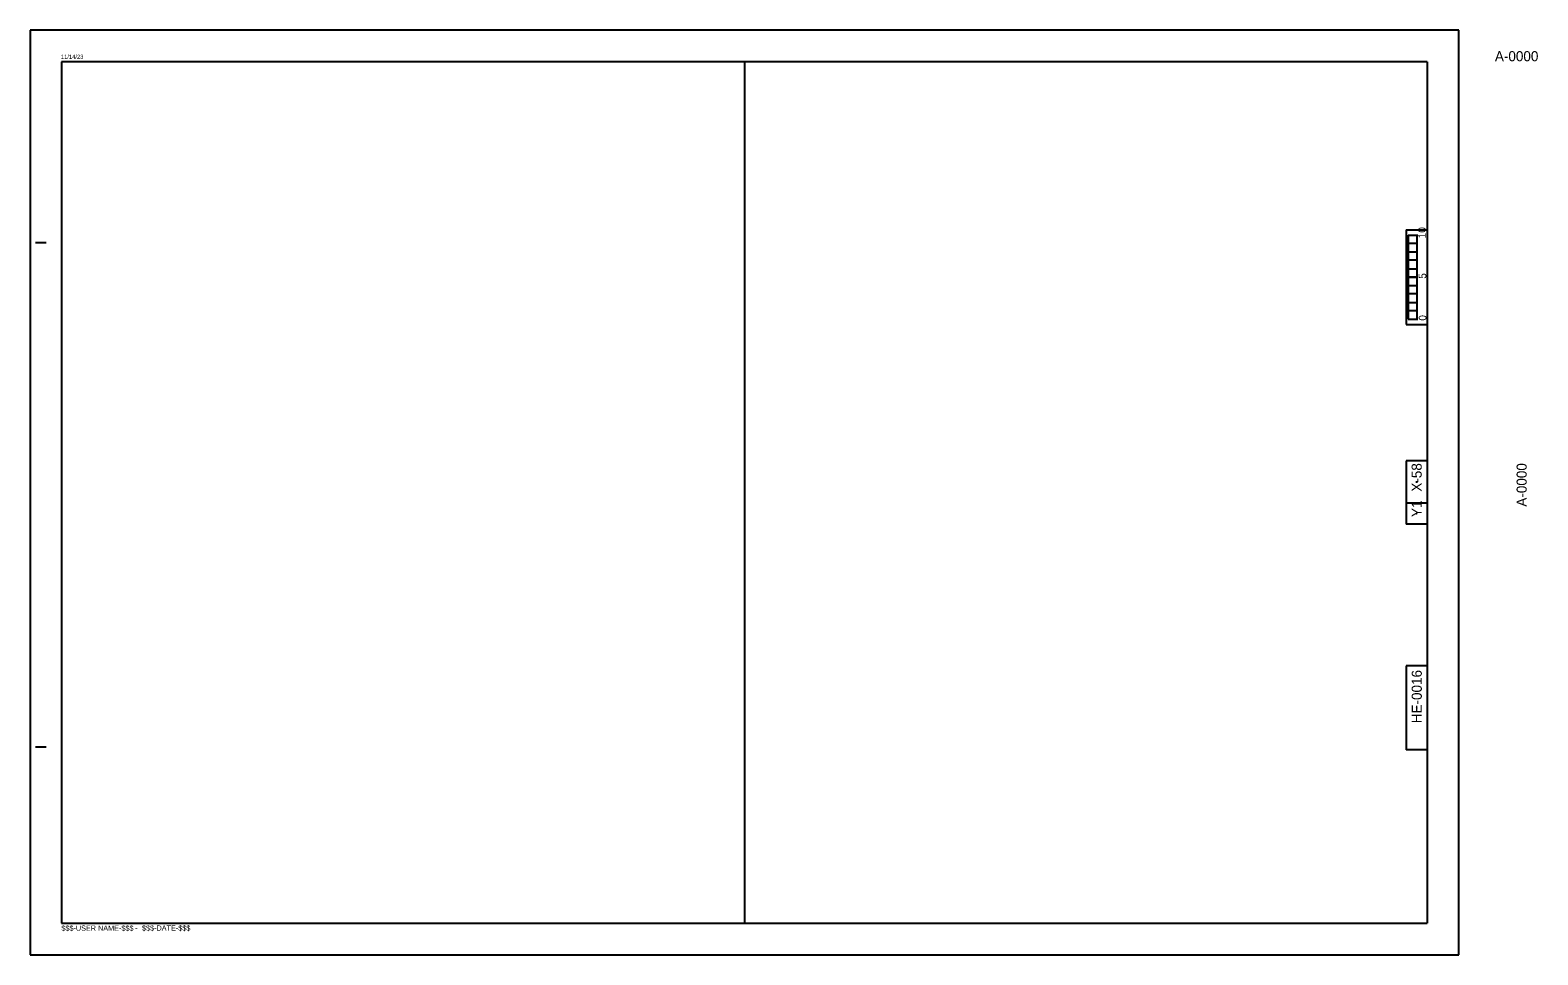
# Model space of a CAD drawing. Extents: x -2.69 to 2.99, y 0 to 1.83.
# Drawn here: x 0 to 2.99, y 0 to 1.833 of the extents above; entities that cross this region are included whole.
import ezdxf

# ---------------------------------------------------------------- set-up
doc = ezdxf.new("R2010")
doc.units = 0
for name, color, linetype in [('P_NCDOT_XS_Sheet_Alignment_Station_Label', 7, 'Continuous'), ('P_NCDOT_XS_Sheet_Annotation_Label', 7, 'Continuous'), ('Sheet_Grid_Major', 7, 'Continuous'), ('Sheet_Grid_Middle', 7, 'Continuous'), ('Sheet_Grid_Minor', 7, 'Continuous')]:
    doc.layers.add(name, color=color, linetype=linetype)

msp = doc.modelspace()

# ---------------------------------------------------------------- linework, layer by layer
at = {"layer": 'P_NCDOT_XS_Sheet_Alignment_Station_Label'}
for p, q in [((2.7333, 1.4271), (2.7522, 1.4271)), ((2.7333, 1.4271), (2.7333, 1.2604)), ((2.7417, 1.4271), (2.7504, 1.4271)), ((2.75, 1.4271), (2.75, 1.2604)), ((2.7333, 1.3437), (2.7522, 1.3437)), ((2.7333, 1.2604), (2.7522, 1.2604)), ((2.7417, 1.2604), (2.7504, 1.2604))]:
    msp.add_line(p, q, dxfattribs=at)
for points in [[(2.7333, 1.4271), (2.75, 1.4271), (2.75, 1.4104), (2.7333, 1.4104)], [(2.7333, 1.3937), (2.75, 1.3937), (2.75, 1.3771), (2.7333, 1.3771)], [(2.7333, 1.3604), (2.75, 1.3604), (2.75, 1.3437), (2.7333, 1.3437)], [(2.7333, 1.3271), (2.75, 1.3271), (2.75, 1.3104), (2.7333, 1.3104)], [(2.7333, 1.2937), (2.75, 1.2937), (2.75, 1.2771), (2.7333, 1.2771)]]:
    msp.add_lwpolyline(points, close=True, dxfattribs=at)
at = {"layer": 'P_NCDOT_XS_Sheet_Annotation_Label'}
for p, q in [((2.8333, 1.8333), (0, 1.8333)), ((0, 1.8333), (0, 0)), ((2.8333, 0), (2.8333, 1.8333)), ((1.4167, 1.7708), (1.4166, 0.0625)), ((0, 0), (2.8333, 0))]:
    msp.add_line(p, q, dxfattribs=at)
for centre in [(2.7499, 1.3437), (2.7499, 0.9375), (2.7499, 0.875), (2.75, 0.4897)]:
    msp.add_circle(centre, 0.0001, dxfattribs=at)
at = {"layer": 'Sheet_Grid_Minor'}
for p, q in [((0.0625, 1.7708), (0.0625, 0.0625)), ((2.7708, 1.7708), (0.0625, 1.7708)), ((0.1027, 1.7844), (0.1027, 1.7844)), ((2.7708, 1.7708), (2.7708, 0.0625)), ((2.7292, 1.4375), (2.7292, 1.25)), ((2.7292, 1.4375), (2.7708, 1.4375)), ((0.0108, 1.4125), (0.0317, 1.4126)), ((2.7292, 1.25), (2.7708, 1.25)), ((2.7292, 0.9792), (2.7292, 0.8542)), ((2.7708, 0.9792), (2.7292, 0.9792)), ((2.7708, 0.8958), (2.7292, 0.8958)), ((2.7708, 0.8542), (2.7292, 0.8542)), ((2.7292, 0.5729), (2.7292, 0.4062)), ((2.7708, 0.5729), (2.7292, 0.5729)), ((0.0109, 0.4125), (0.0317, 0.4125)), ((2.7708, 0.4062), (2.7292, 0.4062)), ((0.0625, 0.0625), (2.7708, 0.0625))]:
    msp.add_line(p, q, dxfattribs=at)

# ---------------------------------------------------------------- texts
at = {"layer": 'P_NCDOT_XS_Sheet_Alignment_Station_Label'}
for s, p in [('10', (2.7679, 1.4206)), ('5', (2.7689, 1.3404)), ('0', (2.7691, 1.2573))]:
    msp.add_text(s, height=0.015, rotation=90, dxfattribs=at).set_placement(p)
at = {"layer": 'Sheet_Grid_Major'}
msp.add_text('A-0000', height=0.02, dxfattribs=at).set_placement((2.9051, 1.7717))
msp.add_text('A-0000', height=0.02, rotation=90, dxfattribs=at).set_placement((2.9681, 0.8886))
at = {"layer": 'Sheet_Grid_Middle'}
for s, p in [('X-58', (2.7599, 0.9183)), ('Y1', (2.76, 0.8681)), ('HE-0016', (2.7601, 0.4592))]:
    msp.add_text(s, height=0.02, rotation=90, dxfattribs=at).set_placement(p)
at = {"layer": 'Sheet_Grid_Minor'}
msp.add_text('11/14/23', height=0.00833, rotation=0, dxfattribs=at).set_placement((0.0609, 1.7764))
for s, height, p in [('$$$-USER NAME-$$$', 0.010417, (0.0619, 0.0477)), ('-', 0.0104, (0.2081, 0.0487)), ('$$$-DATE-$$$', 0.010417, (0.2218, 0.0479))]:
    msp.add_text(s, height=height, dxfattribs=at).set_placement(p)

doc.saveas('drawing.dxf')
